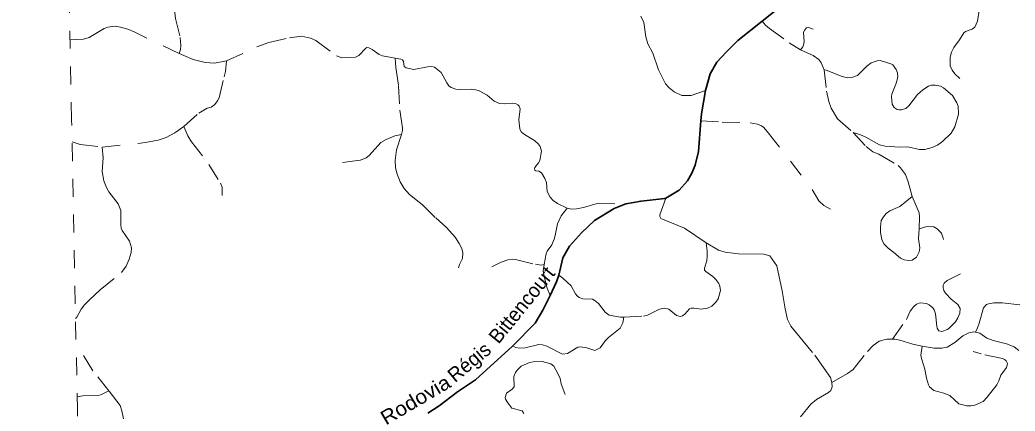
# Model space of a CAD drawing. Extents: x 220.8 to 246.7, y 7287.6 to 7315.8.
# Drawn here: x 220.75 to 226.33, y 7299.01 to 7301.2 of the extents above; entities that cross this region are included whole.
import ezdxf
from ezdxf.enums import TextEntityAlignment as Align

# ---------------------------------------------------------------- set-up
doc = ezdxf.new("R2010")
doc.units = 0
doc.header["$LTSCALE"] = 0.032
for name, pattern in [('DOTTED', [1.5, 0.3, -1.2]), ('LONG_DASHED', [7.5, 6, -1.5]), ('MEDIUM_DASHED', [4.5, 3, -1.5]), ('SHORT_DASHED', [2.7, 1.5, -1.2])]:
    doc.linetypes.add(name, pattern=pattern)
for name, color, linetype, lineweight in [('2', 7, 'Continuous', 35), ('35', 7, 'SHORT_DASHED', 13), ('5', 7, 'LONG_DASHED', 13), ('6', 7, 'MEDIUM_DASHED', 13), ('7', 7, 'DOTTED', 13)]:
    doc.layers.add(name, color=color, linetype=linetype, lineweight=lineweight)
doc.layers.add('61', color=7, linetype='Continuous')

msp = doc.modelspace()

# ---------------------------------------------------------------- linework, layer by layer
at = {"layer": '2'}
msp.add_lwpolyline([(223.0409, 7298.998), (223.1049, 7299.0386), (223.2073, 7299.1174), (223.3096, 7299.1843), (223.5165, 7299.3731), (223.6429, 7299.5018), (223.6875, 7299.574), (223.7273, 7299.6573), (223.7636, 7299.7327), (223.777, 7299.7708), (223.799, 7299.8679), (223.8358, 7299.9322), (223.904, 7300.0083), (223.9761, 7300.0765), (224.0864, 7300.1447), (224.152, 7300.1696), (224.2372, 7300.1854), (224.3711, 7300.1998), (224.3762, 7300.2025), (224.4511, 7300.2457), (224.497, 7300.2995), (224.522, 7300.3415), (224.5416, 7300.3861), (224.5587, 7300.4635), (224.5726, 7300.6348), (224.5758, 7300.6735), (224.5984, 7300.8044), (224.6243, 7300.8978), (224.6624, 7300.9634), (224.7148, 7301.0199), (224.7804, 7301.0841), (224.9169, 7301.193), (225.1163, 7301.3531)], dxfattribs=at)
at = {"layer": '35'}
msp.add_lwpolyline([(221.3035, 7287.6034), (221.271, 7289.2329), (221.2386, 7290.8624), (221.2062, 7292.4919), (221.1738, 7294.1214), (221.1414, 7295.7509), (221.109, 7297.3804), (221.0767, 7299.0099), (221.0443, 7300.6394), (221.0121, 7302.2689), (220.9798, 7303.8984), (220.9475, 7305.5279), (220.9153, 7307.1574), (220.883, 7308.7869), (220.8508, 7310.4164), (220.8187, 7312.0459), (220.7865, 7313.6754), (220.7543, 7315.3049)], dxfattribs=at)
at = {"layer": '5'}
msp.add_lwpolyline([(224.3762, 7300.2025), (224.343, 7300.1086), (224.3421, 7300.0988), (224.3484, 7300.0881), (224.4811, 7300.0328), (224.6018, 7299.9509), (224.6709, 7299.9099), (224.7083, 7299.8992), (224.784, 7299.8894), (224.9266, 7299.8876), (224.9587, 7299.8778), (224.9979, 7299.8226), (225.029, 7299.6818), (225.0451, 7299.582), (225.0584, 7299.5214), (225.0771, 7299.4849), (225.2117, 7299.3219), (225.2999, 7299.1963), (225.3081, 7299.1695), (225.3088, 7299.1446), (225.3025, 7299.125), (225.2892, 7299.1125), (225.2206, 7299.0742), (225.1903, 7299.0475), (225.1309, 7298.9775)], dxfattribs=at)
at = {"layer": '6'}
for points in [[(224.2362, 7301.2212), (224.2524, 7301.186), (224.2651, 7301.1058), (224.2755, 7301.0666), (224.3037, 7301.0141), (224.3349, 7300.9206), (224.3741, 7300.8427), (224.3949, 7300.8197), (224.4226, 7300.7972), (224.4653, 7300.7775), (224.5189, 7300.7764), (224.5984, 7300.8044)], [(224.9169, 7301.193), (224.9346, 7301.1712), (224.9577, 7301.1525), (225.0688, 7301.0725), (225.132, 7301.0334), (225.2022, 7301.0005), (225.2351, 7300.9791), (225.2476, 7300.9605), (225.2637, 7300.9206), (225.2778, 7300.8004), (225.2902, 7300.7435), (225.3027, 7300.7061), (225.3391, 7300.6466), (225.4267, 7300.57), (225.4992, 7300.491), (225.5365, 7300.4607), (225.5712, 7300.4483), (225.6797, 7300.3851), (225.693, 7300.3709), (225.7206, 7300.3336), (225.7357, 7300.2927), (225.758, 7300.2117)], [(225.3081, 7299.1695), (225.3955, 7299.2189), (225.4263, 7299.2415), (225.5072, 7299.3427), (225.5387, 7299.3759), (225.5735, 7299.4001), (225.6164, 7299.4115), (225.6466, 7299.412), (225.6609, 7299.4123), (225.6892, 7299.4066), (225.7621, 7299.384), (225.8143, 7299.3717), (225.8802, 7299.3613), (225.9247, 7299.3605), (225.9539, 7299.3678), (225.9975, 7299.3929), (226.0421, 7299.4301), (226.076, 7299.4471), (226.1027, 7299.4527), (226.1125, 7299.4518), (226.1367, 7299.4455), (226.1764, 7299.4179), (226.2112, 7299.4042), (226.2864, 7299.3864), (226.3293, 7299.3686), (226.356, 7299.3492)], [(221.2539, 7299.1225), (221.1637, 7299.2352), (221.0692, 7299.3873)], [(221.0752, 7299.0893), (221.1076, 7299.0949), (221.1918, 7299.0963), (221.2072, 7299.1006), (221.2539, 7299.1225)], [(221.6588, 7298.3593), (221.6455, 7298.4161), (221.6203, 7298.4715), (221.562, 7298.5515), (221.5389, 7298.5971), (221.4513, 7298.7962), (221.426, 7298.8327), (221.358, 7298.9063), (221.3412, 7298.94), (221.3257, 7299.0101), (221.3159, 7299.0402), (221.2539, 7299.1225)]]:
    msp.add_lwpolyline(points, dxfattribs=at)
msp.add_lwpolyline([(225.758, 7300.2117), (225.7971, 7300.1202), (225.7997, 7300.0979), (225.796, 7300.0305), (225.7935, 7299.9743), (225.8015, 7299.9236), (225.7971, 7299.9005), (225.7811, 7299.8721), (225.7571, 7299.8552), (225.7375, 7299.8534), (225.7135, 7299.8561), (225.6922, 7299.865), (225.6548, 7299.8979), (225.6228, 7299.921), (225.5988, 7299.9459), (225.5881, 7299.9699), (225.5801, 7300.009), (225.5792, 7300.0401), (225.5837, 7300.0766), (225.5961, 7300.0979), (225.6121, 7300.1157), (225.6326, 7300.1308), (225.6877, 7300.1557)], close=True, dxfattribs=at)
at = {"layer": '7'}
for points in [[(221.643, 7301.5169), (221.6491, 7301.4371), (221.6418, 7301.367), (221.6201, 7301.2781), (221.6267, 7301.208), (221.6533, 7301.1016), (221.6569, 7301.0563), (221.6545, 7301.0339), (221.647, 7301.0114)], [(226.1342, 7301.2537), (226.124, 7301.1924), (226.1098, 7301.1595), (226.0934, 7301.1481), (226.0559, 7301.1356), (226.0468, 7301.1276), (226.0224, 7301.0879), (225.9917, 7301.0464), (225.9775, 7301.0197), (225.9712, 7300.9908), (225.9712, 7300.9436), (225.982, 7300.9186), (225.9962, 7300.8988), (226.0258, 7300.8726)], [(221.647, 7301.0114), (221.3946, 7301.1336), (221.3589, 7301.1482), (221.3178, 7301.1602), (221.2888, 7301.1651), (221.2477, 7301.1602), (221.2259, 7301.1524), (221.1419, 7301.101), (221.1111, 7301.0931), (221.0355, 7301.0883)], [(225.132, 7301.0334), (225.145, 7301.0493), (225.1484, 7301.0589), (225.1518, 7301.0782), (225.149, 7301.1308), (225.1558, 7301.1438), (225.1654, 7301.1551), (225.1756, 7301.1585), (225.2022, 7301.1483)], [(221.9133, 7300.9704), (222.0822, 7301.0495), (222.1499, 7301.0739), (222.2666, 7301.0999), (222.3329, 7301.11), (222.3847, 7301.0977), (222.4143, 7301.0847), (222.5288, 7300.999), (222.559, 7300.9882), (222.6361, 7300.9918), (222.6548, 7301.0012), (222.6937, 7301.0423), (222.6995, 7301.0451), (222.7117, 7301.043), (222.729, 7301.0343), (222.7694, 7301.007), (222.7881, 7300.999), (222.8594, 7300.9868)], [(221.9133, 7300.9704), (221.8449, 7300.9577), (221.793, 7300.962), (221.7253, 7300.9777), (221.647, 7301.0114)], [(221.6739, 7300.6041), (221.7579, 7300.6785), (221.8044, 7300.7057), (221.8268, 7300.7123), (221.8468, 7300.7262), (221.8631, 7300.7474), (221.8709, 7300.7637), (221.9, 7300.881), (221.9066, 7300.9106), (221.9133, 7300.9704)], [(222.8594, 7300.9868), (222.8617, 7300.9334), (222.8772, 7300.8307), (222.885, 7300.6946), (222.8998, 7300.5966), (222.9006, 7300.5802), (222.8932, 7300.5577)], [(222.8594, 7300.9868), (222.8911, 7300.981), (222.8997, 7300.9767), (222.9062, 7300.9666), (222.9098, 7300.94), (222.9206, 7300.9313), (222.9624, 7300.9234), (223.0402, 7300.9371), (223.0632, 7300.9393), (223.0791, 7300.9349), (223.1172, 7300.9054), (223.1475, 7300.8471), (223.1597, 7300.8312), (223.1727, 7300.8211), (223.1979, 7300.8118), (223.2202, 7300.8096), (223.2879, 7300.8125), (223.311, 7300.8082), (223.329, 7300.8024), (223.3744, 7300.7779), (223.414, 7300.7448), (223.4428, 7300.7325), (223.4716, 7300.7304), (223.5177, 7300.734), (223.5328, 7300.7311), (223.5465, 7300.7239), (223.5537, 7300.7167), (223.5595, 7300.703), (223.5523, 7300.6396), (223.558, 7300.5899), (223.566, 7300.5734), (223.5833, 7300.5582), (223.6394, 7300.5251), (223.661, 7300.5064), (223.6719, 7300.492), (223.6791, 7300.4646), (223.6697, 7300.4135), (223.6632, 7300.3991), (223.6423, 7300.3738), (223.6402, 7300.3666), (223.6423, 7300.3594), (223.6466, 7300.3551), (223.6646, 7300.3522), (223.6791, 7300.3436), (223.6971, 7300.3126), (223.7071, 7300.2903), (223.7107, 7300.2384), (223.7273, 7300.2067), (223.7453, 7300.188), (223.7691, 7300.1715), (223.8239, 7300.1448)], [(225.2637, 7300.9206), (225.2763, 7300.918), (225.3646, 7300.8824), (225.3957, 7300.8762), (225.4257, 7300.879), (225.4506, 7300.8886), (225.5038, 7300.9418), (225.5281, 7300.9605), (225.5609, 7300.9718), (225.5784, 7300.9724), (225.6379, 7300.9543), (225.6486, 7300.948), (225.6678, 7300.9226), (225.6758, 7300.9033), (225.678, 7300.8841), (225.6741, 7300.8649), (225.6667, 7300.8394), (225.6441, 7300.7851), (225.6424, 7300.7698), (225.6452, 7300.7274), (225.6571, 7300.7098), (225.6729, 7300.6991), (225.6854, 7300.6957), (225.6978, 7300.6968), (225.7216, 7300.7042), (225.7397, 7300.7183), (225.7867, 7300.7817), (225.8172, 7300.8094), (225.8489, 7300.8292), (225.867, 7300.8354), (225.8868, 7300.8354), (225.9168, 7300.8298), (225.9338, 7300.8196), (225.9836, 7300.7766), (226.0085, 7300.7364), (226.0158, 7300.7178), (226.0175, 7300.6714), (225.996, 7300.6018), (225.9762, 7300.5667), (225.9281, 7300.5186), (225.9004, 7300.4988), (225.8698, 7300.4863), (225.828, 7300.4745), (225.7991, 7300.4739), (225.734, 7300.4886), (225.6888, 7300.4875), (225.6062, 7300.4926), (225.5745, 7300.4999), (225.4987, 7300.5429), (225.4687, 7300.5571), (225.4267, 7300.57)], [(224.5726, 7300.6348), (224.6919, 7300.6279), (224.8498, 7300.6245), (224.8898, 7300.6171), (224.9122, 7300.6063), (224.9251, 7300.5974), (224.9528, 7300.5663), (225.0748, 7300.4097), (225.1961, 7300.2505), (225.2341, 7300.1875), (225.2632, 7300.1604), (225.2998, 7300.1407)], [(221.0468, 7300.517), (221.0917, 7300.5025), (221.2164, 7300.4874), (221.4593, 7300.5134), (221.5288, 7300.5267), (221.5753, 7300.5424), (221.6225, 7300.5678), (221.6739, 7300.6041)], [(221.6739, 7300.6041), (221.6959, 7300.5518), (221.7172, 7300.518), (221.8139, 7300.3906), (221.8792, 7300.286), (221.8878, 7300.2639), (221.8886, 7300.2168)], [(222.5624, 7300.4021), (222.6647, 7300.4153), (222.6954, 7300.4274), (222.7132, 7300.4412), (222.7789, 7300.513), (222.8079, 7300.5311), (222.8571, 7300.5503), (222.8932, 7300.5577)], [(222.8932, 7300.5577), (222.8663, 7300.4721), (222.8586, 7300.413), (222.8609, 7300.3733), (222.8679, 7300.3422), (222.8873, 7300.2931), (222.9091, 7300.2558), (222.9387, 7300.2231), (223.0126, 7300.1648), (223.0857, 7300.0916), (223.1472, 7300.038), (223.1954, 7299.9835), (223.218, 7299.9485), (223.232, 7299.9189), (223.2382, 7299.8964), (223.2367, 7299.8645), (223.2188, 7299.8302), (223.2133, 7299.8108)], [(221.0665, 7299.5279), (221.0737, 7299.5345), (221.0975, 7299.5792), (221.1157, 7299.6035), (221.1418, 7299.6301), (221.2048, 7299.6889), (221.3242, 7299.7845), (221.3494, 7299.8209), (221.3676, 7299.8601), (221.3788, 7299.8974), (221.3807, 7299.9231), (221.369, 7299.96), (221.3275, 7300.0197), (221.3228, 7300.0341), (221.32, 7300.0519), (221.32, 7300.1321), (221.3051, 7300.1708), (221.2528, 7300.238), (221.2393, 7300.2609), (221.2249, 7300.2991), (221.2155, 7300.3519), (221.2208, 7300.4276), (221.2164, 7300.4874)], [(223.8239, 7300.1448), (223.7903, 7300.1034), (223.7687, 7300.0573), (223.7567, 7299.9933), (223.7498, 7299.9721), (223.7369, 7299.9394), (223.7106, 7299.9043), (223.7046, 7299.8896), (223.6938, 7299.8304)], [(223.8239, 7300.1448), (223.849, 7300.1405), (223.8757, 7300.1419), (223.9146, 7300.1498), (223.9909, 7300.1722), (224.152, 7300.1696)], [(225.796, 7300.0305), (225.8398, 7300.0431), (225.8795, 7300.041), (225.8983, 7300.0305), (225.9213, 7300.0055), (225.9317, 7299.9783), (225.9338, 7299.97)], [(224.1417, 7299.5352), (224.2511, 7299.5412), (224.2741, 7299.5459), (224.34, 7299.5795), (224.3686, 7299.5859), (224.393, 7299.5795), (224.4354, 7299.544), (224.4571, 7299.5389), (224.4691, 7299.5422), (224.482, 7299.5518), (224.5082, 7299.5809), (224.5179, 7299.5846), (224.5331, 7299.5859), (224.575, 7299.5804), (224.6096, 7299.5855), (224.6336, 7299.5961), (224.6566, 7299.6191), (224.6695, 7299.6385), (224.6824, 7299.6845), (224.6787, 7299.7085), (224.6732, 7299.7228), (224.6571, 7299.7468), (224.64, 7299.7629), (224.5999, 7299.7915), (224.5939, 7299.7993), (224.5926, 7299.8099), (224.6055, 7299.85), (224.6078, 7299.8767), (224.6078, 7299.9062), (224.6018, 7299.9509)], [(223.4007, 7299.8165), (223.4525, 7299.8429), (223.4904, 7299.8555), (223.5151, 7299.8593), (223.5342, 7299.8589), (223.6447, 7299.8311), (223.6764, 7299.8269), (223.6938, 7299.8304)], [(223.6938, 7299.8304), (223.689, 7299.7942), (223.6913, 7299.7707), (223.7106, 7299.697), (223.7273, 7299.6573)], [(223.777, 7299.7708), (223.7995, 7299.7537), (223.8456, 7299.7104), (223.8696, 7299.6652), (223.8788, 7299.6537), (223.8908, 7299.6454), (223.9115, 7299.6375), (223.965, 7299.6352), (223.9802, 7299.6274), (223.9981, 7299.6122), (224.0364, 7299.5624), (224.058, 7299.5454), (224.1226, 7299.5343), (224.1417, 7299.5352)], [(225.6466, 7299.412), (225.7254, 7299.5226), (225.7473, 7299.5678), (225.7667, 7299.5948), (225.7815, 7299.6077), (225.8033, 7299.6153), (225.8375, 7299.6124), (225.8537, 7299.6043), (225.8731, 7299.5882), (225.8812, 7299.5768), (225.8883, 7299.5535), (225.8955, 7299.4846), (225.8983, 7299.4728), (225.9069, 7299.4585), (225.924, 7299.4552), (225.9553, 7299.4666), (225.9658, 7299.4737), (226.0004, 7299.5098), (226.0142, 7299.5307), (226.0247, 7299.5568), (226.0261, 7299.5839), (226.0142, 7299.6062), (225.9757, 7299.6362), (225.9439, 7299.6694), (225.9358, 7299.6837), (225.9316, 7299.7003), (225.932, 7299.7145), (225.9373, 7299.7259), (225.9548, 7299.7411), (226.0285, 7299.7777)], [(226.1125, 7299.4518), (226.1246, 7299.4745), (226.1339, 7299.5022), (226.1573, 7299.588), (226.1752, 7299.6064), (226.1856, 7299.6096), (226.2147, 7299.6156), (226.2625, 7299.6158), (226.5167, 7299.5872), (226.6159, 7299.5816), (226.6678, 7299.5724)], [(223.5165, 7299.3731), (223.5351, 7299.3646), (223.5554, 7299.3623), (223.587, 7299.3641), (223.6647, 7299.3814), (223.6844, 7299.3802), (223.7094, 7299.3724), (223.7966, 7299.3282), (223.8241, 7299.3312), (223.8826, 7299.367), (223.897, 7299.3688), (223.9328, 7299.3635), (223.9776, 7299.3479), (224.0075, 7299.3641), (224.0385, 7299.4041), (224.0552, 7299.4208), (224.1197, 7299.4733), (224.1353, 7299.5032), (224.1417, 7299.5352)], [(225.8143, 7299.3717), (225.8071, 7299.3228), (225.81, 7299.3041), (225.8283, 7299.244), (225.8373, 7299.1942), (225.8484, 7299.1558), (225.8548, 7299.1443), (225.8795, 7299.1234), (225.9348, 7299.1098), (225.9685, 7299.097), (226.0196, 7299.0498), (226.0643, 7299.0391), (226.0865, 7299.0383), (226.1099, 7299.0429), (226.1555, 7299.0634), (226.1785, 7299.0877), (226.2326, 7299.1554), (226.2441, 7299.1775), (226.2552, 7299.2099), (226.2863, 7299.2538), (226.2905, 7299.2653), (226.2914, 7299.2764), (226.285, 7299.29), (226.2756, 7299.2985), (226.2633, 7299.3041), (226.144, 7299.3296), (226.1005, 7299.3428)], [(223.581, 7298.9945), (223.5703, 7299.0104), (223.5134, 7299.0249), (223.4898, 7299.0545), (223.4774, 7299.0759), (223.4761, 7299.0849), (223.4834, 7299.1097), (223.5151, 7299.132), (223.5267, 7299.1457), (223.5245, 7299.2023), (223.5335, 7299.2258), (223.5421, 7299.2391), (223.5648, 7299.2605), (223.611, 7299.2815), (223.632, 7299.2849), (223.6821, 7299.2858), (223.7318, 7299.2729), (223.7485, 7299.2605), (223.7712, 7299.2202), (223.7832, 7299.1924), (223.7896, 7299.1611), (223.8123, 7299.102)]]:
    msp.add_lwpolyline(points, dxfattribs=at)

# ---------------------------------------------------------------- texts
at = {"layer": '61'}
for s, rotation, p in [('Bittencourt', 50.96, (223.5993, 7299.5791)), ('Régis', 39.951, (223.2992, 7299.2526))]:
    msp.add_text(s, height=0.08, rotation=rotation, dxfattribs=at).set_placement(p, align=Align.CENTER)
at = {"layer": '61', "width": 1.1}
msp.add_text('Rodovia', height=0.08, rotation=30.532, dxfattribs=at).set_placement((222.9927, 7299.0373), align=Align.CENTER)

doc.saveas('drawing.dxf')
